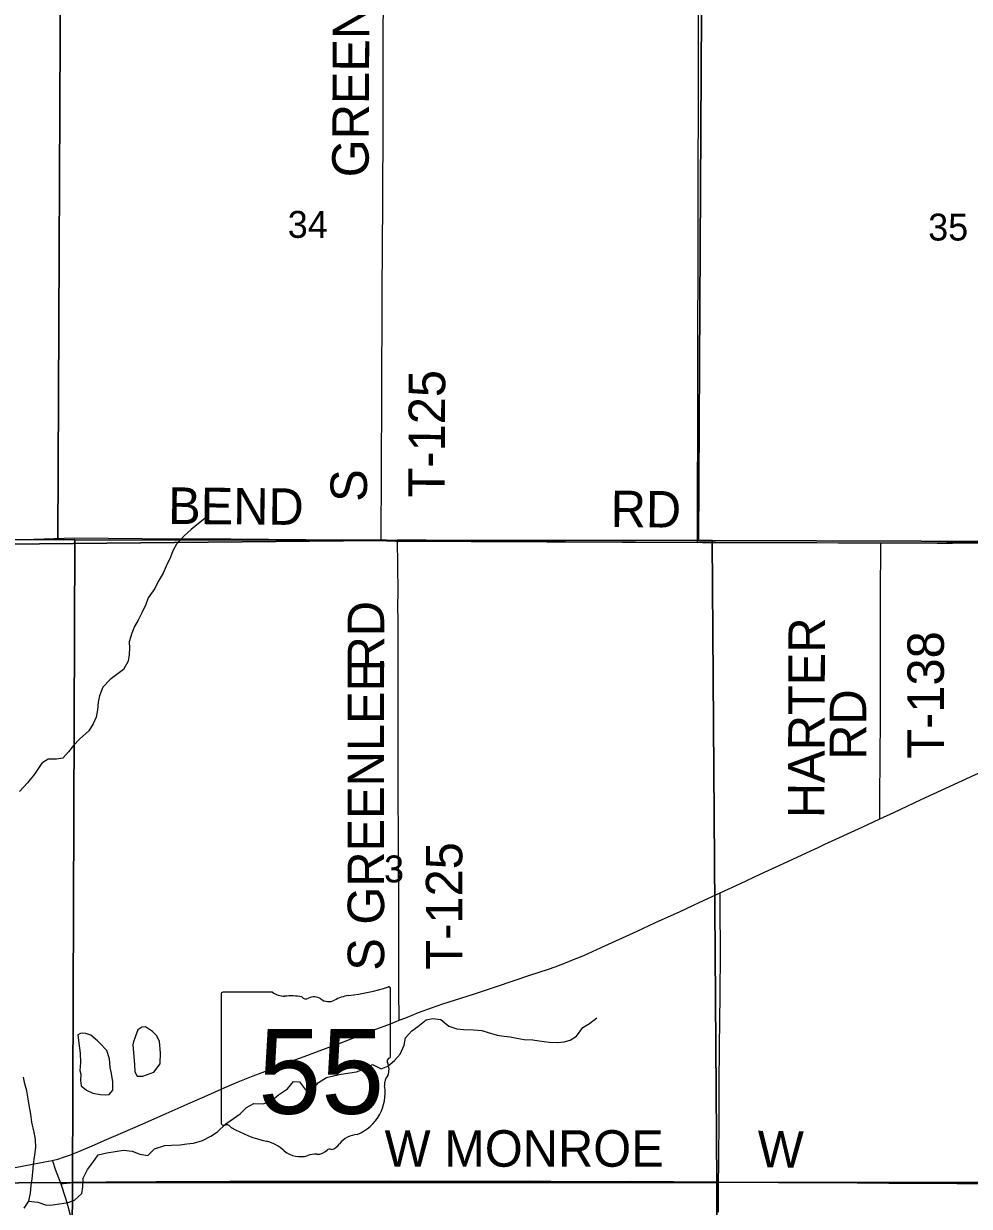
# Model space of a CAD drawing. Extents: x 0 to 680, y 0 to 440.
# Drawn here: x 382.07 to 408.03, y 276.66 to 309.11 of the extents above; entities that cross this region are included whole.
import ezdxf

# ---------------------------------------------------------------- set-up
doc = ezdxf.new("R2010")
doc.units = 0
for name, color, linetype in [('GM_X_County_Road', 7, 'Continuous'), ('GM_X_County_Road_Text', 7, 'Continuous'), ('GM_X_Major_River', 7, 'Continuous'), ('GM_X_Minor_Lake', 7, 'Continuous'), ('GM_X_Minor_River', 7, 'Continuous'), ('GM_X_Section', 7, 'Continuous'), ('GM_X_Section_Text', 7, 'Continuous'), ('GM_X_State_Location', 7, 'Continuous'), ('GM_X_State_Route', 7, 'Continuous'), ('GM_X_State_Shield', 7, 'Continuous'), ('GM_X_Township', 7, 'Continuous'), ('GM_X_Township_Road', 7, 'Continuous'), ('GM_X_Township_Road_Text', 7, 'Continuous')]:
    doc.layers.add(name, color=color, linetype=linetype)

msp = doc.modelspace()

# ---------------------------------------------------------------- linework, layer by layer
at = {"layer": 'GM_X_County_Road'}
for points in [[(380.687, 294.807), (380.743, 294.83), (380.794, 294.85), (380.832, 294.864), (380.865, 294.876), (380.888, 294.883), (380.92, 294.892), (380.947, 294.899), (380.982, 294.906), (381.012, 294.91), (381.043, 294.914), (381.124, 294.922), (381.251, 294.928), (381.372, 294.933), (381.524, 294.938), (383.457, 294.998), (386.255, 294.977), (386.977, 294.979), (387.753, 294.978), (391.88, 294.94)], [(391.88, 294.94), (392.333, 294.944)], [(392.333, 294.944), (393.117, 294.944), (394.672, 294.925), (395.81, 294.909), (396.938, 294.9), (398.001, 294.893), (398.471, 294.889), (399.523, 294.883), (400.059, 294.879), (400.7, 294.878)], [(400.7, 294.878), (401.198, 294.877), (402.052, 294.875), (403.092, 294.874), (403.837, 294.87), (404.428, 294.869), (404.865, 294.867), (405.595, 294.867)], [(405.595, 294.867), (405.72, 294.867), (406.442, 294.862), (407.143, 294.859), (407.559, 294.86), (408.107, 294.862), (408.501, 294.861), (409.377, 294.856), (409.5, 294.856)], [(401.142, 277.335), (401.145, 277.799), (401.154, 279.19), (401.16, 280.088), (401.175, 281.828), (401.183, 282.376), (401.19, 282.836), (401.192, 283.241), (401.19, 285.263)], [(401.139, 276.496), (401.139, 276.89), (401.142, 277.335)], [(401.142, 277.335), (402.029, 277.327), (402.785, 277.319), (403.53, 277.315), (404.318, 277.31), (404.949, 277.306), (405.818, 277.299), (406.672, 277.294), (407.68, 277.287), (408.479, 277.285), (409.41, 277.275), (410.715, 277.276), (411.915, 277.279), (412.657, 277.279), (413.627, 277.282), (414.702, 277.287), (415.598, 277.287), (416.397, 277.29), (416.989, 277.296), (417.481, 277.298), (418.269, 277.296), (418.514, 277.296)]]:
    msp.add_lwpolyline(points, dxfattribs=at)
at = {"layer": 'GM_X_Major_River'}
msp.add_lwpolyline([(382.08, 276.613), (382.21, 276.806), (382.253, 277.02), (382.276, 277.234), (382.299, 277.414), (382.322, 277.595), (382.338, 277.809), (382.361, 278.01), (382.398, 278.277), (382.394, 278.492), (382.357, 278.693), (382.294, 278.969), (382.263, 279.19), (382.22, 279.439), (382.195, 279.607), (382.151, 279.828), (382.1, 280.023), (382.063, 280.205)], dxfattribs=at)
at = {"layer": 'GM_X_Minor_Lake'}
for points in [[(384.16, 281.136), (384.097, 281.202), (383.913, 281.361), (383.773, 281.405), (383.693, 281.413), (383.625, 281.402), (383.557, 281.363), (383.586, 281.141), (383.619, 280.865), (383.626, 280.604), (383.607, 280.383)], [(385.314, 281.575), (385.205, 281.504), (385.138, 281.333), (385.069, 281.145), (385.067, 281.091), (385.093, 280.775)], [(385.093, 280.775), (385.108, 280.547), (385.123, 280.352), (385.187, 280.23), (385.342, 280.233), (385.64, 280.346), (385.813, 280.57), (385.82, 280.872), (385.794, 281.181), (385.725, 281.343), (385.606, 281.454), (385.408, 281.586), (385.314, 281.575)], [(383.607, 280.383), (383.632, 280.288), (383.628, 280.114), (383.644, 279.966), (383.796, 279.848), (383.968, 279.77), (384.175, 279.725), (384.309, 279.722), (384.417, 279.733), (384.514, 279.844), (384.513, 280.079), (384.478, 280.308), (384.442, 280.47), (384.427, 280.705), (384.346, 280.935), (384.16, 281.136)]]:
    msp.add_lwpolyline(points, dxfattribs=at)
at = {"layer": 'GM_X_Minor_River'}
for points in [[(387.083, 295.567), (386.866, 295.391), (386.662, 295.234), (386.472, 295.057), (386.261, 294.826), (386.164, 294.647), (386.094, 294.468), (385.983, 294.229), (385.899, 294.03), (385.762, 293.805), (385.665, 293.613), (385.487, 293.355), (385.417, 293.169), (385.312, 292.943), (385.209, 292.744), (385.105, 292.566), (385.036, 292.386), (384.965, 292.147), (384.968, 291.973), (384.966, 291.805), (384.936, 291.619), (384.805, 291.387), (384.628, 291.249), (384.439, 291.119), (384.241, 290.909), (384.15, 290.669), (384.114, 290.489), (384.097, 290.282), (384.054, 290.082), (383.977, 289.896), (383.86, 289.704), (383.602, 289.482), (383.438, 289.304), (383.295, 289.133), (383.138, 288.955), (382.964, 288.931), (382.743, 288.928), (382.567, 288.824), (382.368, 288.514), (382.177, 288.276), (381.952, 288.039)], [(382.21, 276.806), (382.453, 276.777), (382.692, 276.691), (382.867, 276.7), (383.049, 276.729), (383.285, 276.77), (383.467, 276.832), (383.66, 277.016), (383.691, 277.196), (383.697, 277.437), (383.817, 277.675), (383.969, 277.866), (384.108, 278.071), (384.351, 278.132), (384.58, 278.166), (384.809, 278.201), (385.05, 278.175), (385.256, 278.096), (385.477, 278.057), (385.662, 278.234), (385.94, 278.328), (386.128, 278.343), (386.363, 278.351), (386.545, 278.373), (386.733, 278.395), (386.977, 278.463), (387.208, 278.585), (387.385, 278.708), (387.619, 278.923), (387.823, 279.066), (388.008, 279.202), (388.187, 279.372), (388.384, 279.481), (388.645, 279.475), (388.869, 279.557), (389.061, 279.72), (389.313, 279.881), (389.472, 280.085), (389.64, 280.074), (389.802, 279.856), (390.011, 279.884), (390.156, 280.055), (390.381, 280.197), (390.604, 280.252), (390.779, 280.288), (391.203, 280.352), (391.42, 280.434), (391.645, 280.556), (391.883, 280.436), (392.059, 280.505), (392.245, 280.662), (392.403, 280.839), (392.51, 281.078), (392.548, 281.285), (392.721, 281.475), (392.891, 281.598), (393.117, 281.781), (393.299, 281.81), (393.52, 281.791), (393.737, 281.605), (393.957, 281.526), (394.144, 281.515), (394.412, 281.501), (394.647, 281.482), (394.82, 281.431), (395.067, 281.358), (395.254, 281.327), (395.421, 281.31), (395.608, 281.278), (395.809, 281.24), (396.043, 281.228), (396.217, 281.204), (396.491, 281.163), (396.719, 281.151), (396.901, 281.174), (397.07, 281.223), (397.24, 281.327), (397.42, 281.564), (397.598, 281.68), (397.796, 281.836)]]:
    msp.add_lwpolyline(points, dxfattribs=at)
at = {"layer": 'GM_X_Section'}
for points in [[(365.398, 312.641), (383.083, 312.727), (383.007, 294.958), (365.804, 294.95), (365.357, 294.952)], [(400.691, 312.634), (400.595, 294.926), (383.474, 294.949), (383.007, 294.958), (383.083, 312.727)], [(400.691, 312.634), (418.332, 312.54), (418.177, 294.873), (400.962, 294.925), (400.595, 294.926)], [(383.007, 294.958), (383.474, 294.949), (383.405, 277.313), (365.687, 277.203), (365.804, 294.95)], [(400.962, 294.925), (401.095, 277.318), (383.405, 277.313), (383.474, 294.949), (400.595, 294.926)], [(418.177, 294.873), (418.691, 294.863), (418.538, 277.327), (401.095, 277.318), (400.962, 294.925)], [(365.687, 277.203), (383.405, 277.313), (383.298, 259.399), (365.663, 259.44)], [(383.405, 277.313), (401.095, 277.318), (401.107, 259.328), (383.298, 259.399)], [(401.095, 277.318), (418.538, 277.327), (418.503, 259.018), (401.107, 259.328)]]:
    msp.add_lwpolyline(points, close=True, dxfattribs=at)
at = {"layer": 'GM_X_State_Route'}
msp.add_lwpolyline([(381.835, 277.725), (382.646, 277.878), (382.85, 277.922), (382.888, 277.93), (383.005, 277.959), (383.161, 278.006), (383.357, 278.074), (383.581, 278.162), (383.943, 278.316), (384.344, 278.492), (384.785, 278.686), (385.337, 278.926), (385.978, 279.207), (386.637, 279.502), (387.039, 279.676), (387.569, 279.912), (387.953, 280.074), (388.37, 280.241), (388.615, 280.335), (389.036, 280.498), (389.413, 280.64), (389.869, 280.809), (390.183, 280.925), (390.797, 281.157), (391.665, 281.491), (392.135, 281.672), (392.377, 281.767), (392.553, 281.836), (392.909, 281.977), (393.259, 282.107), (393.57, 282.214), (394.415, 282.483), (395.05, 282.691), (395.963, 282.999), (396.471, 283.17), (396.658, 283.234), (396.821, 283.295), (396.986, 283.357), (397.115, 283.411), (397.44, 283.545), (397.92, 283.758), (398.905, 284.21), (399.412, 284.444), (400.09, 284.753), (400.436, 284.916), (400.625, 285.004), (401.19, 285.263), (401.74, 285.516), (402.285, 285.77), (402.722, 285.973), (403.04, 286.12), (403.556, 286.359), (403.873, 286.508), (404.062, 286.595), (405.087, 287.066), (405.571, 287.29), (405.951, 287.466), (406.705, 287.819), (408.515, 288.654)], dxfattribs=at)
at = {"layer": 'GM_X_State_Shield'}
for p, q in [((387.489, 282.478), (387.489, 278.951)), ((388.896, 282.538), (387.535, 282.538)), ((392.136, 280.781), (392.136, 282.626)), ((392.135, 280.781), (392.136, 280.781))]:
    msp.add_line(p, q, dxfattribs=at)
for centre, radius, start, end in [((390.481, 287.347), 4.928, 275.8445, 288.9065), ((392.084, 282.633), 0.0517, 351.8621, 97.738), ((387.542, 282.485), 0.0538, 98.1301, 188.1301), ((389.22, 282.948), 0.522, 231.6195, 271.1119), ((389.393, 280.558), 1.875, 80.4867, 94.9883), ((389.818, 282.503), 0.151, 219.7921, 297.1024), ((390.04, 282.096), 0.313, 54.4667, 119.1411), ((390.444, 282.655), 0.377, 233.8562, 294.8282), ((391.109, 281.461), 0.991, 97.3462, 120.7689), ((392.124, 280.645), 0.0801, 107.944, 210.337), ((392.081, 280.774), 0.0554, 289.6038, 7.7341), ((391.615, 280.412), 0.481, 340.033, 23.6496), ((392.321, 280.009), 0.35, 136.8065, 186.9296), ((390.757, 279.774), 1.233, 292.3089, 8.9858), ((387.543, 278.943), 0.0543, 171.9584, 258.3066), ((387.551, 279.304), 0.414, 267.339, 280.6039), ((387.636, 278.747), 0.149, 29.7484, 93.2717), ((389.523, 281.916), 3.559, 240.4129, 257.1985), ((388.462, 277.366), 1.113, 47.1842, 75.836), ((391.276, 277.961), 0.675, 94.4031, 142.5768), ((389.666, 278.73), 0.707, 230.7004, 286.2918), ((390.074, 277.51), 0.581, 85.6951, 111.2099), ((390.126, 278.466), 0.376, 268.777, 315.5493), ((390.466, 278.124), 0.106, 65.7517, 132.6484), ((390.421, 278.609), 0.398, 282.8732, 323.2771)]:
    msp.add_arc(centre, radius, start, end, dxfattribs=at)
at = {"layer": 'GM_X_Township'}
for points in [[(345.039, 401.013), (345.039, 295.02), (350.497, 294.965), (353.224, 294.93), (357.228, 294.973), (360.054, 294.917), (364.9, 294.96), (369.752, 294.899), (377.006, 294.87), (379.986, 294.818), (380.635, 294.822), (391.775, 294.926), (392.287, 294.912), (400.568, 294.878), (400.602, 312.614), (400.766, 331.273), (400.686, 347.788), (400.683, 361.148)], [(409.368, 294.878), (405.452, 294.857), (400.568, 294.878), (400.602, 312.614), (400.766, 331.273), (400.686, 347.788), (400.683, 361.148), (400.728, 378.698), (400.754, 388.691), (400.762, 391.895), (400.786, 400.996), (418.142, 400.971)], [(418.103, 188.464), (418.29, 277.524), (418.638, 293.332), (418.665, 294.82), (409.368, 294.878), (405.452, 294.857), (392.287, 294.912), (391.775, 294.926), (380.635, 294.822), (379.986, 294.818), (377.006, 294.87), (369.752, 294.899), (364.9, 294.96), (360.054, 294.917), (357.228, 294.973), (353.224, 294.93), (350.497, 294.965), (345.039, 295.02), (345.039, 188.757)]]:
    msp.add_lwpolyline(points, dxfattribs=at)
at = {"layer": 'GM_X_Township_Road'}
for points in [[(391.88, 294.94), (391.879, 295.017), (391.877, 295.488), (391.885, 296.287), (391.888, 297.218), (391.898, 298.554), (391.898, 299.441), (391.903, 299.952), (391.905, 300.544), (391.908, 301.746), (391.922, 304.213), (391.925, 304.894), (391.932, 305.715), (391.939, 306.646), (391.939, 308.804), (391.948, 309.712), (391.95, 309.986), (391.952, 310.161), (391.955, 310.676), (391.957, 311.092), (391.956, 311.917), (391.956, 312.472), (391.957, 312.536), (391.96, 312.596)], [(392.377, 281.767), (392.375, 281.894), (392.364, 282.473), (392.363, 282.899), (392.363, 284.814), (392.354, 286.485), (392.351, 288.281), (392.349, 288.489), (392.348, 288.663), (392.347, 288.958), (392.346, 289.417), (392.346, 289.735), (392.345, 291.147), (392.346, 291.486), (392.345, 291.738), (392.343, 292.351), (392.343, 292.712), (392.342, 293.128), (392.344, 293.522), (392.333, 294.944)], [(405.571, 287.29), (405.572, 288.14), (405.579, 288.688), (405.582, 289.104), (405.588, 289.903), (405.586, 290.626), (405.585, 291.337), (405.587, 291.95), (405.59, 293.472), (405.595, 294.777), (405.595, 294.867)], [(382.85, 277.922), (382.864, 277.881), (382.936, 277.679), (382.982, 277.559), (383.086, 277.282)], [(383.086, 277.282), (383.159, 277.29), (383.245, 277.3), (383.266, 277.303), (383.292, 277.305), (383.315, 277.306), (383.34, 277.307), (383.47, 277.311), (384.324, 277.331), (385.707, 277.342), (386.67, 277.344), (387.063, 277.346), (387.73, 277.348), (388.507, 277.353), (389.414, 277.355), (390.058, 277.353), (390.811, 277.354), (391.566, 277.352), (392.135, 277.356), (392.934, 277.35), (393.59, 277.351), (395.019, 277.355), (395.944, 277.357), (396.535, 277.352), (397.925, 277.346), (398.724, 277.348), (399.905, 277.343), (400.737, 277.336), (401.076, 277.335), (401.142, 277.335)], [(383.086, 277.282), (383.214, 276.882), (383.291, 276.624), (383.337, 276.453), (383.36, 276.369), (383.381, 276.274), (383.399, 276.184), (383.417, 276.065), (383.438, 275.919), (383.473, 275.664), (383.561, 275.053), (383.685, 274.187), (383.744, 273.775), (383.759, 273.684), (383.762, 273.667)]]:
    msp.add_lwpolyline(points, dxfattribs=at)

# ---------------------------------------------------------------- texts
at = {"layer": 'GM_X_County_Road_Text'}
for s, height, rotation, p in [('BEND', 1.0014, 359.4956, (386.03, 295.386)), ('RD', 1.0014, 359.5085, (398.177, 295.297)), ('W', 1.001, 359.2913, (402.209, 277.732))]:
    msp.add_text(s, height=height, rotation=rotation, dxfattribs=at).set_placement(p)
at = {"layer": 'GM_X_Section_Text'}
for s, height, p in [('34', 0.7377, (389.316, 303.232)), ('35', 0.7377, (406.896, 303.159)), ('3', 0.738, (391.96, 285.549))]:
    msp.add_text(s, height=height, rotation=0, dxfattribs=at).set_placement(p)
at = {"layer": 'GM_X_State_Location'}
for s in ['s', 'r']:
    msp.add_text(s, height=0.00334, dxfattribs=at).set_placement((389.76, 280.48))
msp.add_text('55', height=0.00334, rotation=0, dxfattribs=at).set_placement((388.92, 280.237))
at = {"layer": 'GM_X_State_Shield'}
msp.add_text('55', height=2.3235, dxfattribs=at).set_placement((388.506, 279.199))
at = {"layer": 'GM_X_Township_Road_Text'}
for s, height, rotation, p in [('GREENLEE', 1.0014, 89.7412, (391.536, 304.891)), ('T-125', 1.0014, 89.7193, (393.624, 296.107)), ('S', 1.001, 90, (391.492, 295.99)), ('RD', 1.0014, 90, (391.963, 291.335)), ('HARTER', 1.0014, 89.8286, (404.047, 287.31)), ('T-138', 1.0014, 90, (407.327, 288.941)), ('GREENLEE', 1.0014, 90, (391.962, 284.388)), ('RD', 1.0014, 90, (405.195, 288.912)), ('T-125', 1.0014, 90, (394.109, 283.154)), ('S', 1.001, 90, (391.962, 283.125)), ('W MONROE', 1.0014, 0, (391.974, 277.747))]:
    msp.add_text(s, height=height, rotation=rotation, dxfattribs=at).set_placement(p)

doc.saveas('drawing.dxf')
